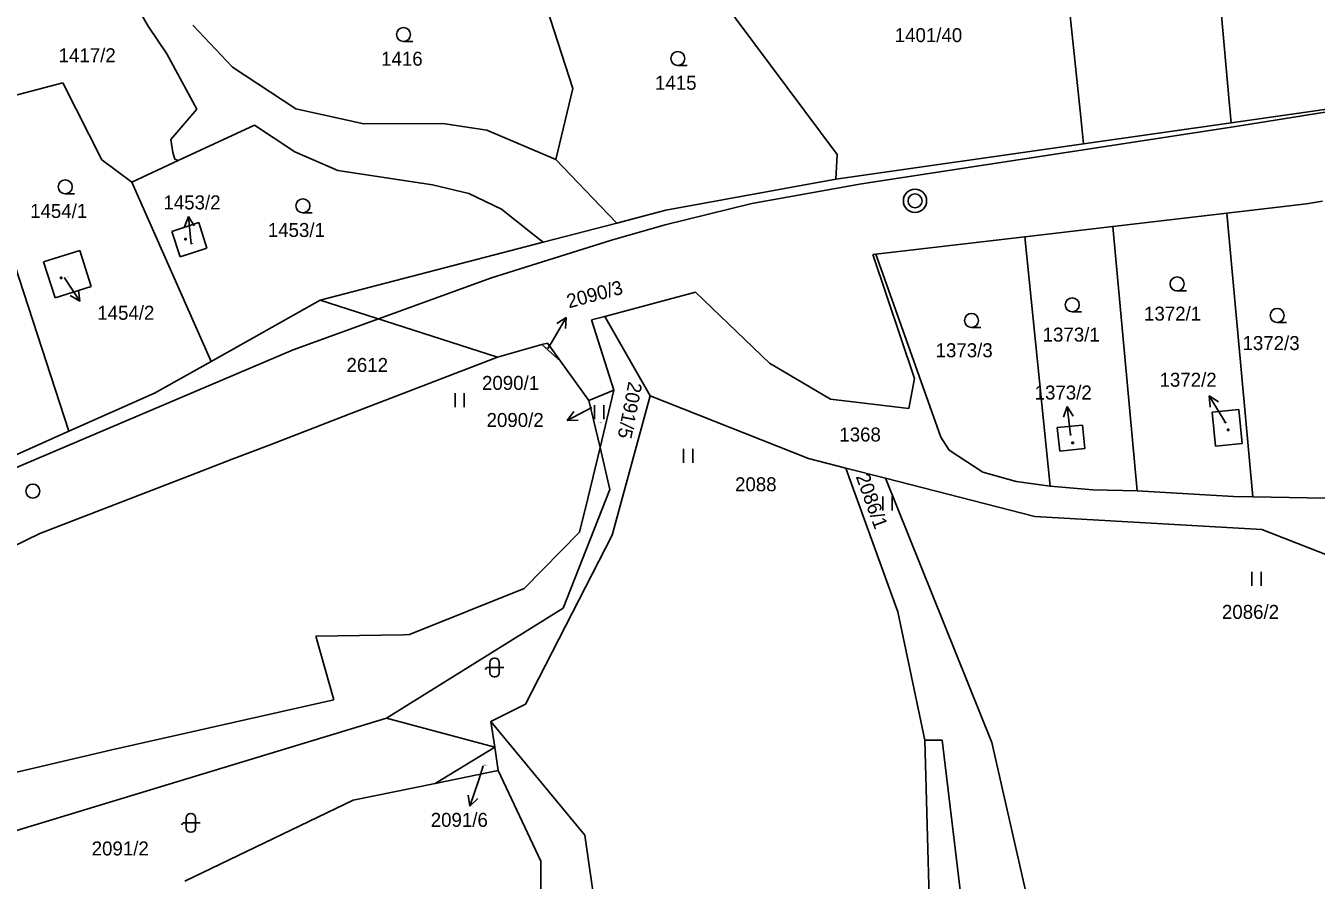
# Model space of a CAD drawing. Extents: x -805730 to -804640, y -1150889 to -1150366.
# Drawn here: x -804924.5 to -804785.9, y -1150604.7 to -1150513 of the extents above; entities that cross this region are included whole.
import ezdxf

# ---------------------------------------------------------------- set-up
doc = ezdxf.new("R2010")
doc.units = 0
for name, color, linetype in [('Default', 7, 'Continuous'), ('kilometráž - vrstava 7', 7, 'Continuous'), ('kn_celek - Cisla parcel pomocna', 7, 'Continuous'), ('kn_celek - Cisla pozemkovych parcel', 7, 'Continuous'), ('kn_celek - Cisla stavebnich parcel', 7, 'Continuous'), ('kn_celek - Hranice parcel', 7, 'Continuous'), ('kn_celek - Znacky budov', 7, 'Continuous'), ('kn_celek - Znacky kultur', 7, 'Continuous'), ('plochy - SZDC', 7, 'Continuous'), ('PSR_C2_2_trasa_Vimperk - Kabelová trasa', 7, 'Continuous')]:
    doc.layers.add(name, color=color, linetype=linetype)

# ---------------------------------------------------------------- blocks, each defined once
blk = doc.blocks.new('304')
at = {"layer": 'Default'}
blk.add_line((-0.1, 0), (9.9, 0), dxfattribs=at)
blk.add_circle((-0.1, 7.5), 7.5, dxfattribs=at)
blk = doc.blocks.new('306')
at = {"layer": 'Default'}
for p, q in [((-5.2, 0), (-5.2, 15)), ((4.8, 0), (4.8, 15))]:
    blk.add_line(p, q, dxfattribs=at)
blk = doc.blocks.new('316')
at = {"layer": 'Default'}
for p, q in [((-5, 15.5), (-5, 4.5)), ((0.5, 20), (-0.5, 20)), ((5, 4.5), (5, 15.5)), ((-8.3, 10), (-10, 8.1)), ((-5, 10), (-8.3, 10)), ((-5, 10), (5, 10)), ((-0.5, 0), (0.5, 0)), ((10, 10), (5, 10))]:
    blk.add_line(p, q, dxfattribs=at)
for centre, start, end in [((-0.5, 15.5), 90, 180), ((0.5, 15.5), 0, 90), ((-0.5, 4.5), 180, 270), ((0.5, 4.5), 270, 0)]:
    blk.add_arc(centre, 4.5, start, end, dxfattribs=at)
blk = doc.blocks.new('402')
at = {"layer": 'Default'}
for p, q in [((-0.8, 0.8), (0.7, 0.8)), ((-0.8, 0.8), (-0.8, -0.7)), ((0.7, 0.8), (0.7, -0.7)), ((0.7, -0.7), (-0.8, -0.7))]:
    blk.add_line(p, q, dxfattribs=at)
blk = doc.blocks.new('Z61')
at = {"layer": 'Default'}
for p, q in [((0, 0), (30, 0)), ((30, 0), (19.2, 5.3)), ((30, 0), (19.2, -5.3))]:
    blk.add_line(p, q, dxfattribs=at)

msp = doc.modelspace()

# ---------------------------------------------------------------- linework, layer by layer
at = {"layer": 'kilometráž - vrstava 7'}
for centre, radius in [((-804829, -1150531.81), 1.25), ((-804829, -1150531.81), 0.752), ((-804923.76, -1150562.97), 0.75)]:
    msp.add_circle(centre, radius, dxfattribs=at)
at = {"layer": 'kn_celek - Cisla parcel pomocna'}
for p, q in [((-804868.43, -1150547.68), (-804867.98, -1150546.92)), ((-804795.62, -1150555.68), (-804795.84, -1150555.31)), ((-804812.29, -1150556.99), (-804812.3, -1150556.88)), ((-804875.37, -1150592.47), (-804875.87, -1150593.97))]:
    msp.add_line(p, q, dxfattribs=at)
at = {"layer": 'kn_celek - Hranice parcel'}
for p, q in [((-804797.37, -1150497.46), (-804795.25, -1150521.16)), ((-804813.68, -1150499.24), (-804811.2, -1150522.83)), ((-804854.06, -1150504.46), (-804837.36, -1150526.82)), ((-804870.5, -1150505.04), (-804865.77, -1150519.74)), ((-804914.77, -1150507.17), (-804911.38, -1150513.07)), ((-804911.38, -1150513.07), (-804909.35, -1150516.02)), ((-804902.3, -1150517.47), (-804906.56, -1150512.95)), ((-804909.35, -1150516.02), (-804906.16, -1150521.98)), ((-804895.5, -1150521.92), (-804902.3, -1150517.47)), ((-804920.55, -1150519.13), (-804925.98, -1150520.59)), ((-804920.55, -1150519.13), (-804916.36, -1150527.41)), ((-804865.77, -1150519.74), (-804867.58, -1150527.37)), ((-804919.88, -1150556.55), (-804931.17, -1150521.99)), ((-804906.16, -1150521.98), (-804908.94, -1150525.24)), ((-804888.2, -1150523.55), (-804895.5, -1150521.92)), ((-804795.25, -1150521.16), (-804795.05, -1150523.42)), ((-804779.36, -1150521.18), (-804795.05, -1150523.42)), ((-804908.15, -1150527.49), (-804899.94, -1150523.69)), ((-804899.94, -1150523.69), (-804895.6, -1150526.55)), ((-804879.72, -1150523.51), (-804888.2, -1150523.55)), ((-804874.99, -1150524.22), (-804879.72, -1150523.51)), ((-804811.2, -1150522.83), (-804810.9, -1150525.68)), ((-804795.05, -1150523.42), (-804810.9, -1150525.68)), ((-804908.94, -1150525.24), (-804908.74, -1150526.63)), ((-804867.58, -1150527.37), (-804874.99, -1150524.22)), ((-804908.74, -1150526.63), (-804908.49, -1150527.35)), ((-804895.6, -1150526.55), (-804891, -1150528.55)), ((-804810.9, -1150525.68), (-804837.49, -1150529.49)), ((-804916.36, -1150527.41), (-804913.13, -1150529.8)), ((-804908.15, -1150527.49), (-804913.13, -1150529.8)), ((-804908.49, -1150527.35), (-804908.26, -1150527.45)), ((-804908.26, -1150527.45), (-804908.15, -1150527.49)), ((-804867.58, -1150527.37), (-804861.97, -1150533.23)), ((-804837.49, -1150529.49), (-804837.36, -1150526.82)), ((-804891, -1150528.55), (-804880.82, -1150530.09)), ((-804904.62, -1150549.05), (-804913.13, -1150529.8)), ((-804880.82, -1150530.09), (-804876.91, -1150531.02)), ((-804837.49, -1150529.49), (-804855.75, -1150532.82)), ((-804876.91, -1150531.02), (-804873.43, -1150532.72)), ((-804795.52, -1150533.13), (-804786.96, -1150532.13)), ((-804786.96, -1150532.13), (-804785.22, -1150531.85)), ((-804873.43, -1150532.72), (-804870.09, -1150535.34)), ((-804861.97, -1150533.23), (-804861.04, -1150534.2)), ((-804855.75, -1150532.82), (-804861.04, -1150534.2)), ((-804807.75, -1150534.56), (-804795.52, -1150533.13)), ((-804795.52, -1150533.13), (-804792.7, -1150563.59)), ((-804908.82, -1150535.1), (-804905.94, -1150534.15)), ((-804905.94, -1150534.15), (-804905.08, -1150536.89)), ((-804861.04, -1150534.2), (-804868.93, -1150536.25)), ((-804817.19, -1150535.66), (-804807.75, -1150534.56)), ((-804807.75, -1150534.56), (-804805.12, -1150562.96)), ((-804907.92, -1150537.83), (-804908.82, -1150535.1)), ((-804868.93, -1150536.25), (-804892.91, -1150542.49)), ((-804870.09, -1150535.34), (-804868.93, -1150536.25)), ((-804833.21, -1150537.53), (-804817.19, -1150535.66)), ((-804814.48, -1150562.46), (-804817.19, -1150535.66)), ((-804922.62, -1150538.35), (-804918.73, -1150537.14)), ((-804918.73, -1150537.14), (-804917.51, -1150541.02)), ((-804905.08, -1150536.89), (-804907.92, -1150537.83)), ((-804833.52, -1150537.57), (-804833.21, -1150537.53)), ((-804833.52, -1150537.57), (-804829.05, -1150550.88)), ((-804833.21, -1150537.53), (-804826.21, -1150557.2)), ((-804921.35, -1150542.23), (-804922.62, -1150538.35)), ((-804917.51, -1150541.02), (-804921.35, -1150542.23)), ((-804862.3, -1150544.21), (-804852.58, -1150541.61)), ((-804844.64, -1150549.24), (-804852.58, -1150541.61)), ((-804904.62, -1150549.05), (-804892.91, -1150542.49)), ((-804873.83, -1150548.59), (-804892.91, -1150542.49)), ((-804863.76, -1150544.6), (-804862.3, -1150544.21)), ((-804861.34, -1150552.12), (-804863.76, -1150544.6)), ((-804862.3, -1150544.21), (-804857.45, -1150552.76)), ((-804869.09, -1150547.25), (-804873.83, -1150548.59)), ((-804868.47, -1150547.08), (-804869.09, -1150547.25)), ((-804867.07, -1150549.03), (-804869.09, -1150547.25)), ((-804867.07, -1150549.03), (-804868.47, -1150547.08)), ((-804873.83, -1150548.59), (-804889.79, -1150554.73)), ((-804904.62, -1150549.05), (-804910.68, -1150552.45)), ((-804864.02, -1150553.26), (-804867.07, -1150549.03)), ((-804838.07, -1150553.11), (-804844.64, -1150549.24)), ((-804829.05, -1150550.88), (-804829.67, -1150554.12)), ((-804919.88, -1150556.55), (-804910.68, -1150552.45)), ((-804861.34, -1150552.12), (-804864.02, -1150553.26)), ((-804862.83, -1150558.29), (-804861.34, -1150552.12)), ((-804861.53, -1150567.7), (-804857.45, -1150552.76)), ((-804857.45, -1150552.76), (-804840.45, -1150559.48)), ((-804862.83, -1150558.29), (-804864.02, -1150553.26)), ((-804829.67, -1150554.12), (-804838.07, -1150553.11)), ((-804797.08, -1150554.49), (-804794.23, -1150554.22)), ((-804794.23, -1150554.22), (-804793.87, -1150557.85)), ((-804889.79, -1150554.73), (-804898.28, -1150557.99)), ((-804796.71, -1150558.14), (-804797.08, -1150554.49)), ((-804919.88, -1150556.55), (-804930.31, -1150561.21)), ((-804813.72, -1150556.16), (-804811.01, -1150555.88)), ((-804813.46, -1150558.69), (-804813.72, -1150556.16)), ((-804811.01, -1150555.88), (-804810.75, -1150558.41)), ((-804898.28, -1150557.99), (-804902.34, -1150559.55)), ((-804864.15, -1150563.75), (-804862.83, -1150558.29)), ((-804861.77, -1150562.79), (-804862.83, -1150558.29)), ((-804826.21, -1150557.2), (-804825.34, -1150558.58)), ((-804810.75, -1150558.41), (-804813.46, -1150558.69)), ((-804793.87, -1150557.85), (-804796.71, -1150558.14)), ((-804902.34, -1150559.55), (-804906.85, -1150561.29)), ((-804836.43, -1150560.51), (-804840.45, -1150559.48)), ((-804825.34, -1150558.58), (-804821.71, -1150560.94)), ((-804906.85, -1150561.29), (-804923.02, -1150567.51)), ((-804836.07, -1150561.51), (-804836.43, -1150560.51)), ((-804836.43, -1150560.51), (-804832.17, -1150561.6)), ((-804821.71, -1150560.94), (-804818.13, -1150561.93)), ((-804830.85, -1150575.93), (-804836.07, -1150561.51)), ((-804832.17, -1150561.6), (-804816.13, -1150565.71)), ((-804832.17, -1150561.6), (-804820.76, -1150589.98)), ((-804818.13, -1150561.93), (-804814.48, -1150562.46)), ((-804814.48, -1150562.46), (-804809.9, -1150562.82)), ((-804866.78, -1150575.55), (-804861.77, -1150562.79)), ((-804865.03, -1150567.37), (-804864.15, -1150563.75)), ((-804809.9, -1150562.82), (-804805.12, -1150562.96)), ((-804805.12, -1150562.96), (-804794.78, -1150563.55)), ((-804794.78, -1150563.55), (-804792.7, -1150563.59)), ((-804792.7, -1150563.59), (-804784.86, -1150563.74)), ((-804816.13, -1150565.71), (-804791.75, -1150567.1)), ((-804923.02, -1150567.51), (-804951.89, -1150581.61)), ((-804870.98, -1150573.44), (-804865.03, -1150567.37)), ((-804870.83, -1150585.85), (-804861.53, -1150567.7)), ((-804791.75, -1150567.1), (-804780.37, -1150571.54)), ((-804883.31, -1150578.38), (-804870.98, -1150573.44)), ((-804885.76, -1150587.34), (-804866.78, -1150575.55)), ((-804830.85, -1150575.93), (-804827.95, -1150589.7)), ((-804893.36, -1150578.56), (-804891.02, -1150578.52)), ((-804891.43, -1150585.39), (-804893.36, -1150578.56)), ((-804891.02, -1150578.52), (-804883.96, -1150578.39)), ((-804883.96, -1150578.39), (-804883.31, -1150578.38)), ((-804915.29, -1150590.76), (-804891.43, -1150585.39)), ((-804874.55, -1150587.71), (-804870.83, -1150585.85)), ((-804942.25, -1150604.51), (-804885.76, -1150587.34)), ((-804874.15, -1150590.46), (-804885.76, -1150587.34)), ((-804874.55, -1150587.71), (-804864.48, -1150599.92)), ((-804874.55, -1150587.71), (-804874.15, -1150590.46)), ((-804827.95, -1150589.7), (-804827.34, -1150611.64)), ((-804827.95, -1150589.7), (-804826.08, -1150589.72)), ((-804826.08, -1150589.72), (-804823.4, -1150611.86)), ((-804820.76, -1150589.98), (-804815.75, -1150611.81)), ((-804941.23, -1150596.81), (-804915.29, -1150590.76)), ((-804880.53, -1150594.36), (-804874.15, -1150590.46)), ((-804874.15, -1150590.46), (-804873.79, -1150592.97)), ((-804873.79, -1150592.97), (-804880.53, -1150594.36)), ((-804869.21, -1150602.7), (-804873.79, -1150592.97)), ((-804880.53, -1150594.36), (-804889.34, -1150596.17)), ((-804889.34, -1150596.17), (-804907.43, -1150604.85)), ((-804864.48, -1150599.92), (-804859.64, -1150632.81)), ((-804869.15, -1150627.88), (-804869.21, -1150602.7))]:
    msp.add_line(p, q, dxfattribs=at)
at = {"layer": 'plochy - SZDC'}
for p, q in [((-804779.36, -1150521.18), (-804795.05, -1150523.42)), ((-804795.05, -1150523.42), (-804810.9, -1150525.68)), ((-804810.9, -1150525.68), (-804837.49, -1150529.49)), ((-804837.49, -1150529.49), (-804855.75, -1150532.82)), ((-804795.52, -1150533.13), (-804786.96, -1150532.13)), ((-804786.96, -1150532.13), (-804785.22, -1150531.85)), ((-804855.75, -1150532.82), (-804861.04, -1150534.2)), ((-804807.75, -1150534.56), (-804795.52, -1150533.13)), ((-804861.04, -1150534.2), (-804868.93, -1150536.25)), ((-804817.19, -1150535.66), (-804807.75, -1150534.56)), ((-804868.93, -1150536.25), (-804892.91, -1150542.49)), ((-804833.21, -1150537.53), (-804817.19, -1150535.66)), ((-804833.52, -1150537.57), (-804833.21, -1150537.53)), ((-804829.05, -1150550.88), (-804833.52, -1150537.57)), ((-804862.3, -1150544.21), (-804852.58, -1150541.61)), ((-804852.58, -1150541.61), (-804844.64, -1150549.24)), ((-804892.91, -1150542.49), (-804904.62, -1150549.05)), ((-804873.83, -1150548.59), (-804892.91, -1150542.49)), ((-804892.91, -1150542.49), (-804873.83, -1150548.59)), ((-804863.76, -1150544.6), (-804862.3, -1150544.21)), ((-804861.34, -1150552.12), (-804863.76, -1150544.6)), ((-804873.83, -1150548.59), (-804869.09, -1150547.25)), ((-804869.09, -1150547.25), (-804868.47, -1150547.08)), ((-804889.79, -1150554.73), (-804873.83, -1150548.59)), ((-804904.62, -1150549.05), (-804910.68, -1150552.45)), ((-804867.07, -1150549.03), (-804864.02, -1150553.26)), ((-804844.64, -1150549.24), (-804838.07, -1150553.11)), ((-804829.67, -1150554.12), (-804829.05, -1150550.88)), ((-804910.68, -1150552.45), (-804919.88, -1150556.55)), ((-804864.02, -1150553.26), (-804861.34, -1150552.12)), ((-804838.07, -1150553.11), (-804829.67, -1150554.12)), ((-804898.28, -1150557.99), (-804889.79, -1150554.73)), ((-804919.88, -1150556.55), (-804930.31, -1150561.21)), ((-804902.34, -1150559.55), (-804898.28, -1150557.99)), ((-804906.85, -1150561.29), (-804902.34, -1150559.55)), ((-804923.02, -1150567.51), (-804906.85, -1150561.29)), ((-804951.89, -1150581.61), (-804923.02, -1150567.51))]:
    msp.add_line(p, q, dxfattribs=at)
msp.add_lwpolyline([(-804868.47, -1150547.08), (-804868.25, -1150547.38), (-804867.07, -1150549.03)], dxfattribs=at)
at = {"layer": 'PSR_C2_2_trasa_Vimperk - Kabelová trasa'}
for p, q in [((-804846.51, -1150532.09), (-804855.83, -1150534.4)), ((-804855.83, -1150534.4), (-804861.61, -1150536.05))]:
    msp.add_line(p, q, dxfattribs=at)
for points in [[(-804766.6, -1150519.35), (-804794.79, -1150523.86), (-804834.76, -1150530), (-804846.51, -1150532.09)], [(-804861.61, -1150536.05), (-804874.49, -1150540.07), (-804895.8, -1150547.79), (-804932.46, -1150563.38), (-804958.05, -1150574.66), (-804991.35, -1150588.71)]]:
    msp.add_lwpolyline(points, dxfattribs=at)

# ---------------------------------------------------------------- block references
at = {"layer": 'kn_celek - Cisla parcel pomocna'}
for p, xscale, yscale, rotation in [((-804906.74, -1150536.47), 0.1, 0.09999999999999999, 96.00903), ((-804920.37, -1150540.08), 0.1, 0.09999999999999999, -56.30985), ((-804867.98, -1150546.92), 0.1, 0.10000000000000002, 59.542020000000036), ((-804795.84, -1150555.31), 0.1, 0.09999999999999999, 121.27914000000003), ((-804863.71, -1150554.01), 0.1, 0.10000000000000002, -152.56035), ((-804812.3, -1150556.88), 0.09999999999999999, 0.10000000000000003, 96.64524000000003), ((-804875.87, -1150593.97), 0.09999999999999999, 0.1, -108.49419)]:
    msp.add_blockref('Z61', p, dxfattribs=dict(at, xscale=xscale, yscale=yscale, rotation=rotation))
at = {"layer": 'kn_celek - Znacky budov', "xscale": 0.1, "yscale": 0.10000000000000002}
for p in [(-804907.37, -1150535.93), (-804920.72, -1150540.08), (-804795.36, -1150556.41), (-804812.06, -1150557.79)]:
    msp.add_blockref('402', p, dxfattribs=at)
at = {"layer": 'kn_celek - Znacky kultur', "xscale": 0.1, "yscale": 0.10000000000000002}
for name, p in [('304', (-804883.93, -1150514.7)), ('304', (-804854.47, -1150517.28)), ('304', (-804920.27, -1150531.05)), ('304', (-804894.74, -1150533.09)), ('304', (-804800.84, -1150541.48)), ('304', (-804812.1, -1150543.72)), ('304', (-804822.92, -1150545.4)), ('304', (-804790.09, -1150544.86)), ('306', (-804877.89, -1150553.97)), ('306', (-804862.89, -1150555.25)), ('306', (-804853.36, -1150559.93)), ('306', (-804831.92, -1150565.06)), ('306', (-804792.31, -1150573.15)), ('316', (-804874.16, -1150582.92)), ('316', (-804906.79, -1150599.6))]:
    msp.add_blockref(name, p, dxfattribs=at)

# ---------------------------------------------------------------- texts
at = {"layer": 'kn_celek - Cisla parcel pomocna'}
for s, p in [('1453/2', (-804909.73, -1150532.73)), ('1454/2', (-804916.84, -1150544.58)), ('1372/2', (-804802.73, -1150551.77)), ('1373/2', (-804816.15, -1150553.14)), ('2090/2', (-804875.02, -1150556.09)), ('2091/6', (-804881.02, -1150599.02))]:
    msp.add_text(s, height=1.5, dxfattribs=at).set_placement(p)
msp.add_text('2090/3', height=1.5, rotation=15.0491, dxfattribs=at).set_placement((-804866.18, -1150543.36))
at = {"layer": 'kn_celek - Cisla pozemkovych parcel'}
for s, height, p in [('1401/40', 1.5, (-804831.18, -1150514.77)), ('1417/2', 1.5, (-804920.99, -1150516.93)), ('1416', 1.5, (-804886.35, -1150517.3)), ('1415', 1.5, (-804856.93, -1150519.88)), ('1454/1', 1.5, (-804924.05, -1150533.65)), ('1453/1', 1.5, (-804898.52, -1150535.69)), ('1372/1', 1.5, (-804804.4, -1150544.67)), ('1373/1', 1.5, (-804815.29, -1150546.92)), ('1373/3', 1.5, (-804826.79, -1150548.6)), ('1372/3', 1.5, (-804793.82, -1150547.83)), ('2612', 1.5, (-804890.07, -1150550.18)), ('2090/3', 0.1, (-804868.71, -1150547.65)), ('2090/1', 1.5, (-804875.51, -1150552.11)), ('2090/2', 0.1, (-804863.08, -1150555.7)), ('1368', 1.5, (-804837.13, -1150557.65)), ('2088', 1.5, (-804848.33, -1150562.99)), ('2086/2', 1.5, (-804796.03, -1150576.69)), ('2091/6', 0.1, (-804875.37, -1150592.44)), ('2091/2', 1.5, (-804917.44, -1150602.09))]:
    msp.add_text(s, height=height, dxfattribs=at).set_placement(p)
for s, rotation, p in [('2091/5', 258.7988, (-804859.76, -1150551.15)), ('2086/1', 289.8665, (-804835.38, -1150561.4))]:
    msp.add_text(s, height=1.5, rotation=rotation, dxfattribs=at).set_placement(p)
at = {"layer": 'kn_celek - Cisla stavebnich parcel'}
for s, p in [('1453/2', (-804906.74, -1150536.44)), ('1454/2', (-804920.37, -1150540.05)), ('1372/2', (-804795.89, -1150555.65)), ('1373/2', (-804812.56, -1150556.96))]:
    msp.add_text(s, height=0.1, dxfattribs=at).set_placement(p)

doc.saveas('drawing.dxf')
